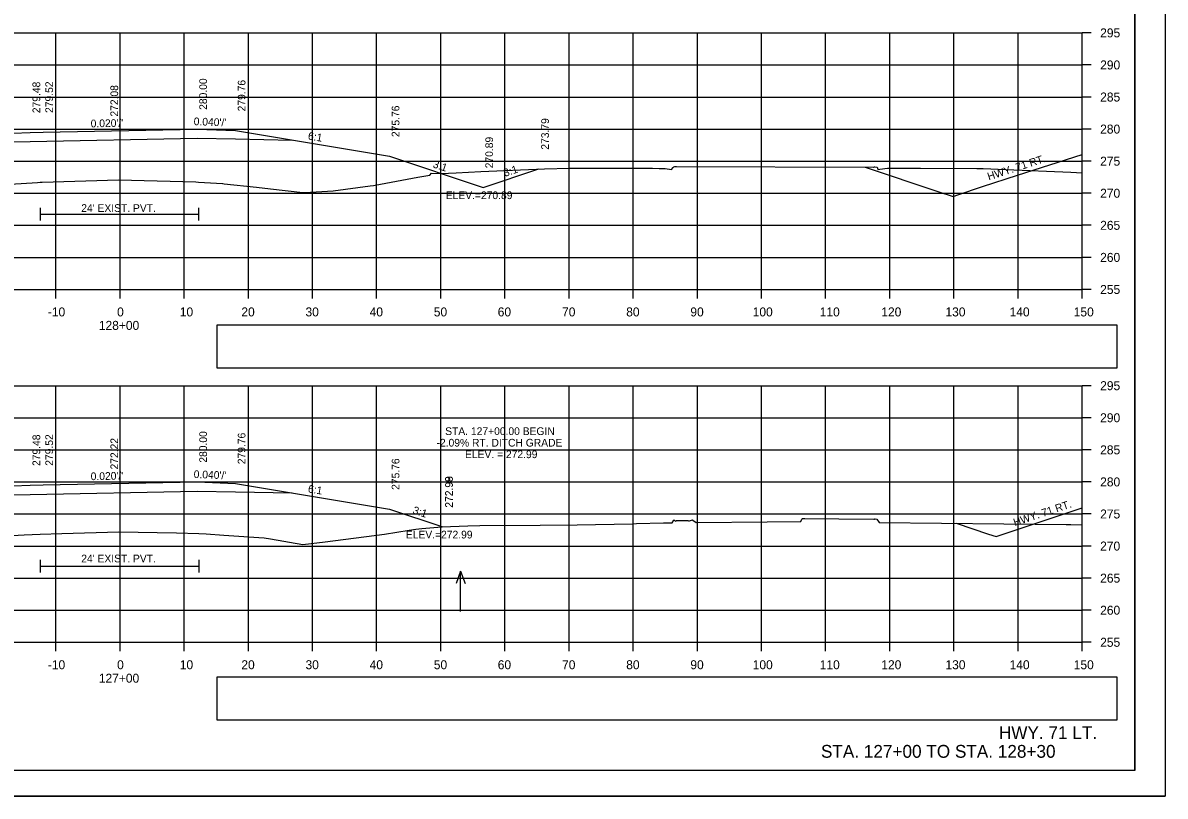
# Model space of a CAD drawing. Extents: x 285 to 4233, y -659 to 3710.
# Drawn here: x 524.1 to 702.2, y 1469.5 to 1590.1 of the extents above; entities that cross this region are included whole.
import ezdxf

# ---------------------------------------------------------------- set-up
doc = ezdxf.new("R2010")
doc.units = 0
for name, color, linetype in [('R_Alt Surface', 7, 'Continuous'), ('R_Axis', 7, 'Continuous'), ('R_Axis Annot', 7, 'Continuous'), ('R_Border', 7, 'Continuous'), ('R_Draft', 7, 'Continuous'), ('R_Exist Surface', 7, 'Continuous'), ('R_Fin Surface', 7, 'Continuous'), ('R_Grid', 7, 'Continuous'), ('R_No Plot', 7, 'Continuous'), ('R_Proposed Const Limits', 7, 'Continuous'), ('R_Water', 7, 'Continuous'), ('R_Water Annot', 7, 'Continuous'), ('R_Xsect Elev', 7, 'Continuous'), ('R_Xsect Slope', 7, 'Continuous')]:
    doc.layers.add(name, color=color, linetype=linetype)

msp = doc.modelspace()

# ---------------------------------------------------------------- linework, layer by layer
at = {"layer": 'R_Alt Surface'}
for points in [[(508.71, 1571.25), (517.28, 1571.42), (525.28, 1571.58), (551.28, 1572.1), (551.28, 1572.1), (557.28, 1571.98), (566.12, 1571.8)], [(526.84, 1561.25), (526.84, 1559.25)], [(526.84, 1560.25), (551.51, 1560.25)], [(551.51, 1561.25), (551.51, 1559.25)], [(508.71, 1516.25), (517.28, 1516.42), (525.28, 1516.58), (551.28, 1517.1), (551.28, 1517.1), (557.28, 1516.98), (566.12, 1516.8)], [(526.82, 1506.39), (526.82, 1504.39)], [(526.82, 1505.39), (551.58, 1505.39)], [(551.58, 1506.39), (551.58, 1504.39)]]:
    msp.add_lwpolyline(points, dxfattribs=at)
at = {"layer": 'R_Axis'}
for p, q in [((689.28, 1548.52), (689.28, 1588.52)), ((690.68, 1588.52), (689.28, 1588.52)), ((690.68, 1583.52), (689.28, 1583.52)), ((690.68, 1578.52), (689.28, 1578.52)), ((690.68, 1573.52), (689.28, 1573.52)), ((690.68, 1568.52), (689.28, 1568.52)), ((690.68, 1563.52), (689.28, 1563.52)), ((690.68, 1558.52), (689.28, 1558.52)), ((690.68, 1553.52), (689.28, 1553.52)), ((389.28, 1548.52), (689.28, 1548.52)), ((529.28, 1547.12), (529.28, 1548.52)), ((539.28, 1547.12), (539.28, 1548.52)), ((549.28, 1547.12), (549.28, 1548.52)), ((559.28, 1547.12), (559.28, 1548.52)), ((569.28, 1547.12), (569.28, 1548.52)), ((579.28, 1547.12), (579.28, 1548.52)), ((589.28, 1547.12), (589.28, 1548.52)), ((599.28, 1547.12), (599.28, 1548.52)), ((609.28, 1547.12), (609.28, 1548.52)), ((619.28, 1547.12), (619.28, 1548.52)), ((629.28, 1547.12), (629.28, 1548.52)), ((639.28, 1547.12), (639.28, 1548.52)), ((649.28, 1547.12), (649.28, 1548.52)), ((659.28, 1547.12), (659.28, 1548.52)), ((669.28, 1547.12), (669.28, 1548.52)), ((679.28, 1547.12), (679.28, 1548.52)), ((689.28, 1547.12), (689.28, 1548.52)), ((690.68, 1548.52), (689.28, 1548.52)), ((689.28, 1493.52), (689.28, 1533.52)), ((690.68, 1533.52), (689.28, 1533.52)), ((690.68, 1528.52), (689.28, 1528.52)), ((690.68, 1523.52), (689.28, 1523.52)), ((690.68, 1518.52), (689.28, 1518.52)), ((690.68, 1513.52), (689.28, 1513.52)), ((690.68, 1508.52), (689.28, 1508.52)), ((690.68, 1503.52), (689.28, 1503.52)), ((690.68, 1498.52), (689.28, 1498.52)), ((389.28, 1493.52), (689.28, 1493.52)), ((529.28, 1492.12), (529.28, 1493.52)), ((539.28, 1492.12), (539.28, 1493.52)), ((549.28, 1492.12), (549.28, 1493.52)), ((559.28, 1492.12), (559.28, 1493.52)), ((569.28, 1492.12), (569.28, 1493.52)), ((579.28, 1492.12), (579.28, 1493.52)), ((589.28, 1492.12), (589.28, 1493.52)), ((599.28, 1492.12), (599.28, 1493.52)), ((609.28, 1492.12), (609.28, 1493.52)), ((619.28, 1492.12), (619.28, 1493.52)), ((629.28, 1492.12), (629.28, 1493.52)), ((639.28, 1492.12), (639.28, 1493.52)), ((649.28, 1492.12), (649.28, 1493.52)), ((659.28, 1492.12), (659.28, 1493.52)), ((669.28, 1492.12), (669.28, 1493.52)), ((679.28, 1492.12), (679.28, 1493.52)), ((689.28, 1492.12), (689.28, 1493.52)), ((690.68, 1493.52), (689.28, 1493.52))]:
    msp.add_line(p, q, dxfattribs=at)
at = {"layer": 'R_Axis Annot'}
for points in [[(554.36, 1536.29), (694.72, 1536.29), (694.72, 1542.94), (554.36, 1542.94)], [(554.36, 1481.45), (694.72, 1481.45), (694.72, 1488.1), (554.36, 1488.1)]]:
    msp.add_lwpolyline(points, close=True, dxfattribs=at)
at = {"layer": 'R_Border'}
for q in [(697.46, 1678.98), (381.28, 1473.52)]:
    msp.add_line((697.46, 1473.52), q, dxfattribs=at)
at = {"layer": 'R_Exist Surface'}
for points in [[(517.81, 1564.7), (526.43, 1565.22), (526.82, 1565.25), (526.84, 1565.25), (527.12, 1565.26), (539.04, 1565.61), (551.08, 1565.28), (551.51, 1565.27), (555.23, 1565.03), (555.32, 1565.03), (555.53, 1565.01), (560.56, 1564.47), (562.71, 1564.22), (567.78, 1563.62), (568.95, 1563.71), (572.52, 1563.92), (578.25, 1564.66), (578.78, 1564.73), (579.04, 1564.78), (585.69, 1566.04), (587.57, 1566.33), (587.85, 1566.67), (589.27, 1566.58), (591.7, 1566.71), (595.52, 1566.91), (605.43, 1567.35), (609.35, 1567.44), (610.32, 1567.44), (613.31, 1567.45), (622.3, 1567.43), (623.31, 1567.38), (624.26, 1567.37), (625.27, 1567.21), (625.49, 1567.52), (625.59, 1567.66), (625.77, 1567.69), (625.84, 1567.7), (625.91, 1567.7), (626.04, 1567.68), (656.72, 1567.59), (656.77, 1567.59), (656.78, 1567.59), (656.78, 1567.59), (656.79, 1567.59), (656.92, 1567.62), (656.94, 1567.62), (657.26, 1567.6), (657.31, 1567.58), (657.31, 1567.59), (657.4, 1567.28), (657.42, 1567.21), (657.45, 1567.22), (657.74, 1567.25), (658.93, 1567.43), (659.95, 1567.45), (664.05, 1567.43), (672.84, 1567.38), (673.82, 1567.36), (677.36, 1567.22), (687.5, 1566.79), (689.28, 1566.71)], [(517.75, 1509.9), (524.35, 1510.26), (526.82, 1510.39), (530.18, 1510.48), (539.1, 1510.74), (548.06, 1510.56), (551.58, 1510.49), (552.7, 1510.41), (555.46, 1510.23), (560.91, 1509.87), (561.74, 1509.81), (561.74, 1509.79), (562.72, 1509.64), (567.8, 1508.79), (571.25, 1509.2), (580.51, 1510.37), (584.36, 1511), (585.41, 1511.18), (586.34, 1511.25), (589.46, 1511.5), (593.51, 1511.65), (595.38, 1511.72), (604.79, 1511.78), (610.56, 1511.81), (619.16, 1512.01), (619.81, 1512.02), (623.99, 1512.12), (625.36, 1512.15), (625.6, 1512.56), (625.62, 1512.59), (625.63, 1512.59), (625.9, 1512.4), (625.9, 1512.41), (625.97, 1512.49), (627.79, 1512.52), (627.82, 1512.5), (627.92, 1512.43), (628.05, 1512.46), (628.53, 1512.63), (628.58, 1512.54), (629.09, 1512.21), (640.19, 1512.3), (645.41, 1512.33), (645.59, 1512.69), (645.65, 1512.81), (645.88, 1512.83), (645.93, 1512.84), (646.01, 1512.83), (646.03, 1512.83), (651.32, 1512.77), (656.81, 1512.72), (656.81, 1512.72), (656.81, 1512.71), (656.81, 1512.71), (656.85, 1512.72), (656.9, 1512.73), (656.97, 1512.74), (657.01, 1512.74), (657.02, 1512.74), (657.24, 1512.71), (657.26, 1512.69), (657.6, 1512.21), (686.78, 1511.87), (687.5, 1511.86), (689.28, 1511.81)]]:
    msp.add_lwpolyline(points, dxfattribs=at)
at = {"layer": 'R_Fin Surface'}
for points in [[(468.46, 1560.33), (469.35, 1560.03), (497.28, 1569.35), (517.28, 1572.68), (525.28, 1573), (527.28, 1573.04), (551.28, 1573.52), (557.28, 1573.28), (581.28, 1569.28), (595.88, 1564.41), (604.59, 1567.31)], [(655.42, 1567.6), (666.78, 1563.81), (669.15, 1563.03), (669.89, 1563.27), (673.72, 1564.55), (679.21, 1566.34), (689.28, 1569.57)], [(468.74, 1506.42), (471.12, 1505.63), (497.28, 1514.35), (517.28, 1517.68), (525.28, 1518), (527.28, 1518.04), (551.28, 1518.52), (557.28, 1518.28), (581.28, 1514.28), (589.61, 1511.5), (589.62, 1511.51)], [(669.64, 1512.07), (674.69, 1510.39), (675.86, 1510), (689.28, 1514.47)]]:
    msp.add_lwpolyline(points, dxfattribs=at)
at = {"layer": 'R_Grid'}
for p, q in [((389.28, 1588.52), (689.28, 1588.52)), ((529.28, 1548.52), (529.28, 1588.52)), ((539.28, 1548.52), (539.28, 1588.52)), ((549.28, 1548.52), (549.28, 1588.52)), ((559.28, 1548.52), (559.28, 1588.52)), ((569.28, 1548.52), (569.28, 1588.52)), ((579.28, 1548.52), (579.28, 1588.52)), ((589.28, 1548.52), (589.28, 1588.52)), ((599.28, 1548.52), (599.28, 1588.52)), ((609.28, 1548.52), (609.28, 1588.52)), ((619.28, 1548.52), (619.28, 1588.52)), ((629.28, 1548.52), (629.28, 1588.52)), ((639.28, 1548.52), (639.28, 1588.52)), ((649.28, 1548.52), (649.28, 1588.52)), ((659.28, 1548.52), (659.28, 1588.52)), ((669.28, 1548.52), (669.28, 1588.52)), ((679.28, 1548.52), (679.28, 1588.52)), ((689.28, 1548.52), (689.28, 1588.52)), ((389.28, 1583.52), (689.28, 1583.52)), ((389.28, 1578.52), (689.28, 1578.52)), ((389.28, 1573.52), (689.28, 1573.52)), ((389.28, 1568.52), (689.28, 1568.52)), ((389.28, 1563.52), (689.28, 1563.52)), ((389.28, 1558.52), (689.28, 1558.52)), ((389.28, 1553.52), (689.28, 1553.52)), ((389.28, 1548.52), (689.28, 1548.52)), ((389.28, 1533.52), (689.28, 1533.52)), ((529.28, 1493.52), (529.28, 1533.52)), ((539.28, 1493.52), (539.28, 1533.52)), ((549.28, 1493.52), (549.28, 1533.52)), ((559.28, 1493.52), (559.28, 1533.52)), ((569.28, 1493.52), (569.28, 1533.52)), ((579.28, 1493.52), (579.28, 1533.52)), ((589.28, 1493.52), (589.28, 1533.52)), ((599.28, 1493.52), (599.28, 1533.52)), ((609.28, 1493.52), (609.28, 1533.52)), ((619.28, 1493.52), (619.28, 1533.52)), ((629.28, 1493.52), (629.28, 1533.52)), ((639.28, 1493.52), (639.28, 1533.52)), ((649.28, 1493.52), (649.28, 1533.52)), ((659.28, 1493.52), (659.28, 1533.52)), ((669.28, 1493.52), (669.28, 1533.52)), ((679.28, 1493.52), (679.28, 1533.52)), ((689.28, 1493.52), (689.28, 1533.52)), ((389.28, 1528.52), (689.28, 1528.52)), ((389.28, 1523.52), (689.28, 1523.52)), ((389.28, 1518.52), (689.28, 1518.52)), ((389.28, 1513.52), (689.28, 1513.52)), ((389.28, 1508.52), (689.28, 1508.52)), ((389.28, 1503.52), (689.28, 1503.52)), ((389.28, 1498.52), (689.28, 1498.52)), ((389.28, 1493.52), (689.28, 1493.52))]:
    msp.add_line(p, q, dxfattribs=at)
at = {"layer": 'R_No Plot'}
msp.add_line((368.88, 1469.54), (702.21, 1469.54), dxfattribs=at)
for points in [[(368.87, 1682.87), (702.21, 1682.87), (702.21, 1469.54), (368.87, 1469.54)], [(615.2, 1678.98), (634.82, 1678.98), (634.82, 1669.1), (650.93, 1669.1), (674.13, 1669.1), (674.25, 1640.94), (697.46, 1640.94), (697.46, 1473.52), (381.28, 1473.52), (381.28, 1678.98)]]:
    msp.add_lwpolyline(points, close=True, dxfattribs=at)
at = {"layer": 'R_Proposed Const Limits'}
for points in [[(527.28, 1573.04), (527.28, 1573.04), (527.28, 1573.04)], [(551.28, 1573.52), (551.28, 1573.52), (551.28, 1573.52)], [(527.28, 1518.04), (527.28, 1518.04), (527.28, 1518.04)], [(551.28, 1518.52), (551.28, 1518.52), (551.28, 1518.52)], [(589.62, 1511.5), (589.61, 1511.5)]]:
    msp.add_lwpolyline(points, dxfattribs=at)
at = {"layer": 'R_Water Annot'}
for p, q in [((592.38, 1504.61), (591.68, 1502.69)), ((592.38, 1498.32), (592.38, 1504.61)), ((592.38, 1504.61), (593.08, 1502.69))]:
    msp.add_line(p, q, dxfattribs=at)
at = {"layer": 'R_Xsect Elev'}
for p, q in [((539.28, 1565.6), (539.28, 1581.61)), ((539.28, 1510.74), (539.28, 1526.29))]:
    msp.add_line(p, q, dxfattribs=at)

# ---------------------------------------------------------------- texts
at = {"layer": 'R_Axis Annot'}
for s, p in [('295', (692.08, 1587.82)), ('290', (692.08, 1582.82)), ('285', (692.08, 1577.82)), ('280', (692.08, 1572.82)), ('275', (692.08, 1567.82)), ('270', (692.08, 1562.82)), ('265', (692.08, 1557.82)), ('260', (692.08, 1552.82)), ('255', (692.08, 1547.82)), ('-10', (528.02, 1544.32)), ('0', (538.82, 1544.32)), ('10', (548.59, 1544.32)), ('20', (558.19, 1544.32)), ('30', (568.19, 1544.32)), ('40', (578.19, 1544.32)), ('50', (588.19, 1544.32)), ('60', (598.16, 1544.32)), ('70', (608.19, 1544.32)), ('80', (618.19, 1544.32)), ('90', (628.19, 1544.32)), ('100', (637.91, 1544.32)), ('110', (648.36, 1544.32)), ('120', (657.96, 1544.32)), ('130', (667.96, 1544.32)), ('140', (677.96, 1544.32)), ('150', (687.96, 1544.32)), ('128+00', (535.97, 1542.22)), ('295', (692.08, 1532.82)), ('290', (692.08, 1527.82)), ('285', (692.08, 1522.82)), ('280', (692.08, 1517.82)), ('275', (692.08, 1512.82)), ('270', (692.08, 1507.82)), ('265', (692.08, 1502.82)), ('260', (692.08, 1497.82)), ('255', (692.08, 1492.82)), ('-10', (528.02, 1489.32)), ('0', (538.82, 1489.32)), ('10', (548.59, 1489.32)), ('20', (558.19, 1489.32)), ('30', (568.19, 1489.32)), ('40', (578.19, 1489.32)), ('50', (588.19, 1489.32)), ('60', (598.16, 1489.32)), ('70', (608.19, 1489.32)), ('80', (618.19, 1489.32)), ('90', (628.19, 1489.32)), ('100', (637.91, 1489.32)), ('110', (648.36, 1489.32)), ('120', (657.96, 1489.32)), ('130', (667.96, 1489.32)), ('140', (677.96, 1489.32)), ('150', (687.96, 1489.32)), ('127+00', (535.97, 1487.22))]:
    msp.add_text(s, height=1.4, dxfattribs=at).set_placement(p)
at = {"layer": 'R_Draft'}
for s, p in [('HWY. 71 LT.', (676.29, 1478.43)), ('STA. 127+00 TO STA. 128+30', (648.55, 1475.52))]:
    msp.add_text(s, height=2, dxfattribs=at).set_placement(p)
at = {"layer": 'R_Water'}
for rotation, p in [(18.0125, (674.72, 1565.51)), (18.4313, (678.77, 1511.6))]:
    msp.add_text('HWY. 71 RT.', height=1.2, rotation=rotation, dxfattribs=at).set_placement(p)
for p in [(533.23, 1560.61), (533.23, 1505.98)]:
    msp.add_text("24' EXIST. PVT.", height=1.2, dxfattribs=at).set_placement(p)
at = {"layer": 'R_Xsect Elev'}
for s, p in [('279.48', (526.83, 1576)), ('279.52', (528.83, 1576.04)), ('272.08', (538.98, 1575.47)), ('280.00', (552.83, 1576.52)), ('279.76', (558.83, 1576.28)), ('275.76', (582.83, 1572.28)), ('273.79', (606.14, 1570.31)), ('270.89', (597.43, 1567.41)), ('280.00', (552.83, 1521.52)), ('279.48', (526.83, 1521)), ('279.52', (528.83, 1521.04)), ('272.22', (538.98, 1520.46)), ('279.76', (558.83, 1521.28)), ('275.76', (582.83, 1517.28)), ('272.98', (591.16, 1514.5)), ('272.99', (591.17, 1514.51))]:
    msp.add_text(s, height=1.2, rotation=90, dxfattribs=at).set_placement(p)
for s, p in [('ELEV.=270.89', (590.06, 1562.61)), ('STA. 127+00.00 BEGIN ', (589.97, 1525.83)), ('-2.09% RT. DITCH GRADE', (588.62, 1524.03)), ('ELEV. = 272.99', (593.06, 1522.23)), ('ELEV.=272.99', (583.84, 1509.71))]:
    msp.add_text(s, height=1.2, dxfattribs=at).set_placement(p)
at = {"layer": 'R_Xsect Slope'}
for s, rotation, p in [("0.020'/'", 1.1458, (534.71, 1573.79)), ("0.040'/'", 357.7094, (550.74, 1574.14)), ('6:1', 350.5377, (568.51, 1571.91)), ('3:1', 341.5651, (587.95, 1567.58)), ('3:1', 18.4349, (599.29, 1566.07)), ("0.020'/'", 1.1458, (534.71, 1518.79)), ("0.040'/'", 357.7094, (550.74, 1519.14)), ('6:1', 350.5377, (568.51, 1516.91)), ('3:1', 341.5651, (584.81, 1513.63))]:
    msp.add_text(s, height=1.2, rotation=rotation, dxfattribs=at).set_placement(p)

doc.saveas('drawing.dxf')
